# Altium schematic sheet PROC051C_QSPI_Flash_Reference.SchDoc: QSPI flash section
size 431 x 279 mm; Date: Not shown in title block; ApprovedBy: Not shown in title block; CheckedBy: Not shown in title block; Author: Not shown in title block; CompanyName: Not shown in title block; Engineer: Not shown in title block; Organization: Not shown in title block; Address1: Not shown in title block; Address2: Not shown in title block; Address3: Not shown in title block; Address4: Not shown in title block; DocumentNumber: 6; Revision: Use project parameter SCH_Rev; SheetNumber: 6; SheetTotal: 16; PageSetup: Record=PageOptions¦CenterHorizontal=True¦CenterVertical=True¦PrintScale=1.00¦XCorrection=1.00¦YCorrection=1.00¦PrintKind=0¦BorderSize=5000000¦LeftOffset=0¦BottomOffset=0¦Orientation=2¦PaperLength=1000¦PaperWidth=1000¦Scale=100¦PaperSource=15¦PrintQuality=600¦MediaType=1¦DitherType=10¦PaperKind=Letter¦PrintScaleMode=1
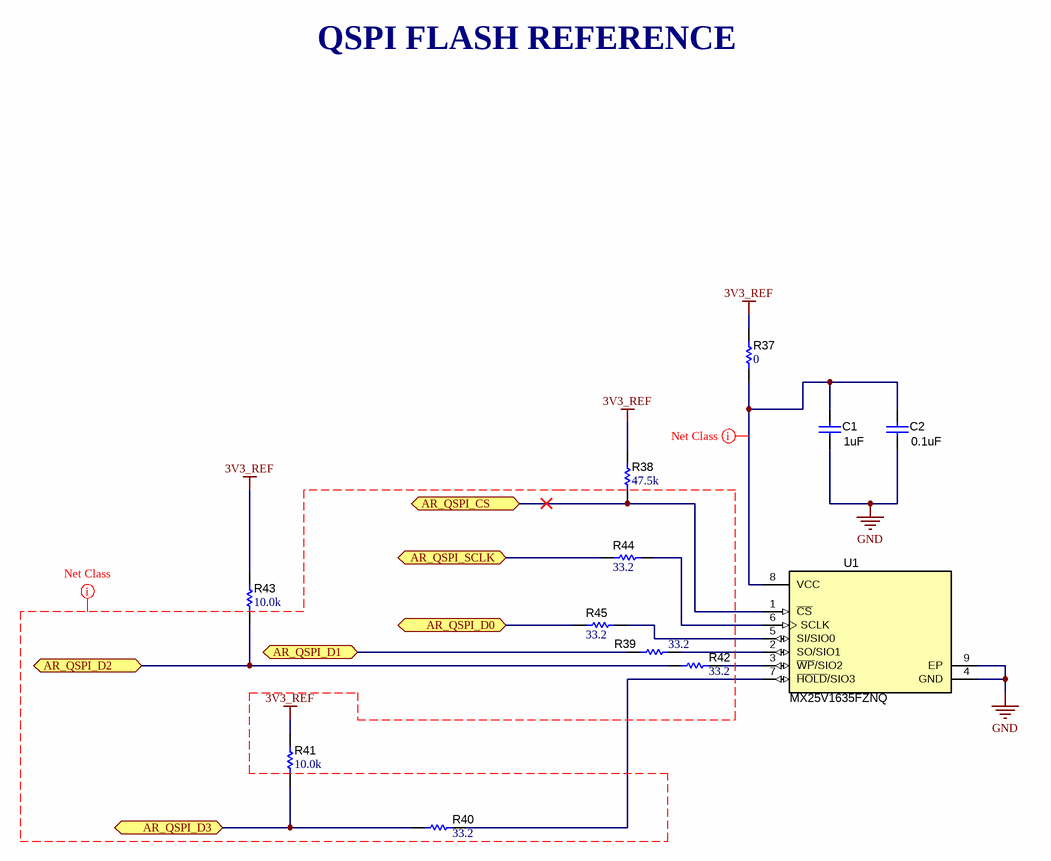
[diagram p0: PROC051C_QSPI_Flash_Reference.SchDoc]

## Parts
C1  ValueDisplayed: 1uF  [0603]  (hidden comment: GCM188R71C105KA64D)
C2  ValueDisplayed: 0.1uF  [0402L]  (hidden comment: CGA2B3X7R1H104K050BB)
R37  ValueDisplayed: 0  [0402L]  (hidden comment: ERJ-2GE0R00X)
R38  ValueDisplayed: 47.5k  [0402L]  (hidden comment: CRCW040247K5FKED)
R39  ValueDisplayed: 33.2  [0201_Silk]  (hidden comment: CRCW020133R2FNED)
R40  ValueDisplayed: 33.2  [0201_Silk]  (hidden comment: CRCW020133R2FNED)
R41  ValueDisplayed: 10.0k  [0402L]  (hidden comment: CRCW040210K0FKED)
R42  ValueDisplayed: 33.2  [0201_Silk]  (hidden comment: CRCW020133R2FNED)
R43  ValueDisplayed: 10.0k  [0402L]  (hidden comment: CRCW040210K0FKED)
R44  ValueDisplayed: 33.2  [0201_Silk]  (hidden comment: CRCW020133R2FNED)
R45  ValueDisplayed: 33.2  [0201_Silk]  (hidden comment: CRCW020133R2FNED)
U1  MX25V1635FZNQ  [WSON-8L_6x5MM_EP]

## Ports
AR_QSPI_CS, AR_QSPI_D0, AR_QSPI_D1, AR_QSPI_D2, AR_QSPI_D3, AR_QSPI_SCLK

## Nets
3V3_REF: R37.1 R38.2 R41.2 R43.2
GND: C1.1 C2.1 U1.4(GND) U1.9(EP)
AR_QSPI_CS: R38.1 U1.1(~{CS}) ; port AR_QSPI_CS
AR_QSPI_D0: R45.2 ; port AR_QSPI_D0
AR_QSPI_D1: R39.1 ; port AR_QSPI_D1
AR_QSPI_D2: R42.1 R43.1 ; port AR_QSPI_D2
AR_QSPI_D3: R40.2 R41.1 ; port AR_QSPI_D3
AR_QSPI_SCLK: R44.2 ; port AR_QSPI_SCLK
NetC1_2: C1.2 C2.2 R37.2 U1.8(VCC)
NetR39_2: R39.2 U1.2(SO/SIO1)
NetR40_1: R40.1 U1.7(~{HOLD}/SIO3)
NetR42_2: R42.2 U1.3(~{WP}/SIO2)
NetR44_1: R44.1 U1.6(SCLK)
NetR45_1: R45.1 U1.5(SI/SIO0)

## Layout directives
net class PWR: NetC1_2
net class QSPI: 3V3_REF

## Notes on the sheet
- QSPI FLASH REFERENCE

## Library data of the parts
C1 = CMP-0007136-5: CAP, CERM, 1 uF, 16 V, +/- 10%, X7R, AEC-Q200 Grade 1, 0603; Manufacturer: MuRata; TaMin_C: -55°C; Polarized: N; SizeAreaWB_mm2: 4.68; Value1: Unknown; U/M: EA; Value: 1uF; TaMax_C: 125°C; SizeZ_mm: 1; SizeX_mm: 1.6; SizeY_mm: 0.8; Value2: 16V; SizeArea_mm2: 1.28; AEC Qualified: Y; Cap_F: 1µF; AEC Category: Q200
C2 = CMP-0006325-2: CAP, CERM, 0.1 uF, 50 V, +/- 10%, X7R, AEC-Q200 Grade 1, 0402; Manufacturer: TDK; TaMin_C: -55°C; ESR_ohm: 0.039064; Polarized: N; SizeAreaWB_mm2: 3; Value1: 0.039064 ohm; U/M: EA; Value: 0.1uF; TaMax_C: 125°C; SizeZ_mm: 0.6; SizeX_mm: 1; SizeY_mm: 0.5; Cap_Case: 0402; Value2: 50V; AEC Qualified: Y; Cap_F: 100nF; IRMS_A: 8.14669dA; AEC Category: Q200
R37 = CMP-0026992-3: RES, 0, 5%, 0.1 W, AEC-Q200 Grade 0, 0402; Manufacturer: Panasonic; Power_W: 100mW; TempCo: 600 ppm/C; Value_Code: 0000; Value: 0; EIA_Code: E24; SizeX_mm: 1; SizeY_mm: 0.5; SizeZ_mm: 0.6; Value2: 0.1W; AEC Qualified: Y; VDC_V: 50V; AEC Category: Q200; SizeAreaWB_mm2: 3
R38 = CMP-0026395-2: RES, 47.5 k, 1%, 0.063 W, AEC-Q200 Grade 0, 0402; Manufacturer: Vishay-Dale; Power_W: 63mW; TempCo: 100 ppm/C; Value_Code: 47k5; Value: 47.5k; EIA_Code: E96; SizeX_mm: 1; SizeY_mm: 0.5; SizeZ_mm: 0.6; Value2: 0.063W; AEC Qualified: Y; VDC_V: 50V; AEC Category: Q200; AEC Grade: 0
R39 R40 R42 R45 = CMP-0027275-3: RES, 33.2, 1%, 0.05 W, 0201; Manufacturer: Vishay-Dale; Power_W: 50mW; TempCo: 200 ppm/C; Value_Code: 33R2; Value: 33.2; EIA_Code: E96; SizeX_mm: 0.6; SizeY_mm: 0.3; SizeZ_mm: 0.26; Value2: 0.05W; SizeArea_mm2: 0.18; AEC Qualified: N; AEC Category: Q200
R41 R43 = CMP-0025958-3: RES, 10.0 k, 1%, 0.063 W, AEC-Q200 Grade 0, 0402; Manufacturer: Vishay-Dale; Power_W: 63mW; TempCo: 100 ppm/C; Value_Code: 10k0; Value: 10.0k; EIA_Code: E96; Res_ohm: 10k; SizeX_mm: 1; SizeY_mm: 0.5; SizeZ_mm: 0.6; Value2: 0.063W; AEC Qualified: Y; VDC_V: 50V; AEC Category: Q200; AEC Grade: 0
R44 = CMP-0027275-3: RES, 33.2, 1%, 0.05 W, 0201; Manufacturer: Vishay-Dale; Power_W: 50mW; TempCo: 200 ppm/C; Value_Code: 33R2; Value: 33.2; EIA_Code: E96; SizeX_mm: 0.6; SizeY_mm: 0.3; SizeZ_mm: 0.26; Value2: 0.05W; SizeArea_mm2: 0.18; CompType: Resistor; AEC Qualified: N; AEC Category: Q200
U1 = CMP-0079267-1: 2.3V-3.6V, 16M-BIT [x 1/x 2/x 4] CMOS FLASH Memory, WSON-8; Manufacturer: Macronix International Co., LTD; SizeArea_mm2: 30; SizeAreaWB_mm2: 56; SizeY_mm: 5; SizeZ_mm: 0.8; SizeX_mm: 6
